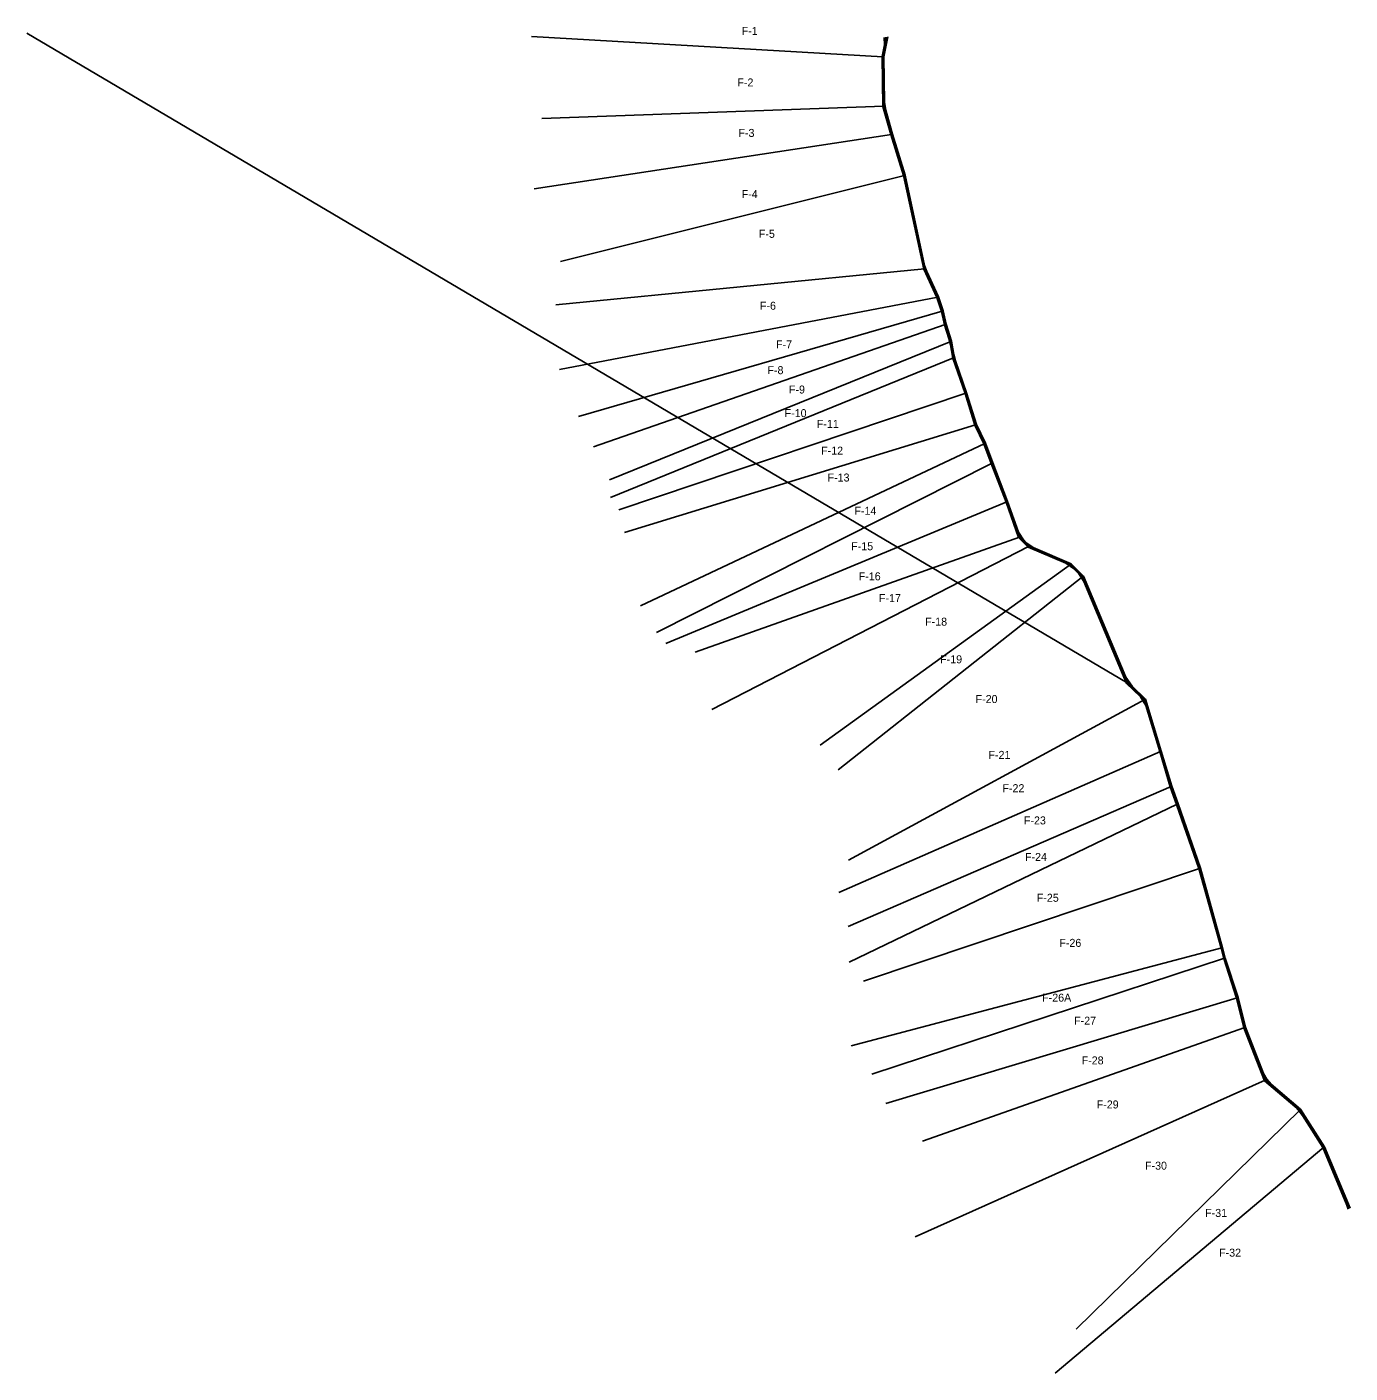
# Model space of a CAD drawing. Extents: x 449105 to 622091, y 1838803 to 1940013.
import ezdxf

# ---------------------------------------------------------------- set-up
doc = ezdxf.new("R2010")
doc.units = 0
for name, color, linetype in [('Level 50', 7, 'Continuous'), ('Level 6', 7, 'Continuous'), ('Level 63', 7, 'Continuous')]:
    doc.layers.add(name, color=color, linetype=linetype)

msp = doc.modelspace()

# ---------------------------------------------------------------- linework, layer by layer
at = {"layer": 'Level 50'}
for p, q in [((587345.381, 1939261.734), (587043.142, 1937770.604)), ((587090.522, 1939228.729), (587095.554, 1938658.427)), ((587214.345, 1939244.496), (587095.554, 1938658.427)), ((587095.554, 1938658.423), (586917.902, 1937781.958)), ((586917.902, 1937781.958), (586989.263, 1934037.384)), ((587043.142, 1937770.604), (587108.194, 1934357.092)), ((587108.194, 1934357.092), (587194.583, 1933764.378)), ((587108.194, 1934357.092), (587113.941, 1934055.538)), ((586989.263, 1934037.384), (587575.849, 1931919.542)), ((587113.941, 1934055.538), (587194.583, 1933764.378)), ((587194.582, 1933764.387), (587695.795, 1931954.78)), ((587575.849, 1931919.542), (588534.712, 1928831.802)), ((587695.795, 1931954.78), (588655.732, 1928863.58)), ((588534.712, 1928831.802), (590052.951, 1921801.885)), ((588655.732, 1928863.58), (590120.935, 1922079.236)), ((590120.933, 1922079.241), (590275.147, 1921622.052)), ((590120.933, 1922079.241), (590172.153, 1921842.077)), ((590052.951, 1921801.885), (591047.278, 1919677.72)), ((590172.153, 1921842.077), (590275.147, 1921622.052)), ((590275.146, 1921622.055), (591163.826, 1919723.582)), ((591047.278, 1919677.72), (591386.753, 1918624.845)), ((591163.826, 1919723.582), (591507.471, 1918657.777)), ((591386.753, 1918624.845), (591611.555, 1917624.298)), ((591507.471, 1918657.777), (591732.269, 1917657.244)), ((591611.555, 1917624.298), (591947.407, 1916582.25)), ((591732.269, 1917657.244), (592144.53, 1916378.124)), ((591947.41, 1916582.239), (592064.936, 1916106.092)), ((591947.41, 1916582.239), (592022.874, 1916348.098)), ((592022.874, 1916348.098), (592064.936, 1916106.092)), ((592064.935, 1916106.097), (592237.461, 1915113.457)), ((592144.53, 1916378.124), (592317.031, 1915385.624)), ((592237.461, 1915113.457), (593155.932, 1912462.15)), ((592317.028, 1915385.635), (592439.06, 1914913.385)), ((592317.028, 1915385.635), (592358.883, 1915144.825)), ((592358.883, 1915144.825), (592439.06, 1914913.385)), ((592439.062, 1914913.378), (593274.772, 1912500.972)), ((593155.932, 1912462.15), (593889.226, 1910068.692)), ((593274.772, 1912500.972), (594005.818, 1910114.85)), ((593889.226, 1910068.692), (594574.897, 1908672.859)), ((594005.818, 1910114.85), (594689.767, 1908722.523)), ((594574.897, 1908672.859), (595130.48, 1907194.846)), ((594689.767, 1908722.523), (595247.264, 1907239.416)), ((595130.48, 1907194.846), (596235.804, 1904291.723)), ((595247.264, 1907239.416), (596353.12, 1904334.899)), ((596235.804, 1904291.723), (597182.919, 1901622.115)), ((596353.12, 1904334.899), (597173.88, 1902021.444)), ((597173.881, 1902021.443), (597537.855, 1901439.936)), ((597173.881, 1902021.443), (597291.445, 1901690.067)), ((597182.919, 1901622.115), (597891.172, 1900903.164)), ((597291.445, 1901690.067), (597537.855, 1901439.936)), ((597401.352, 1901494.389), (597398.879, 1901491.952)), ((597537.857, 1901439.933), (597715.41, 1901259.699)), ((597715.407, 1901259.701), (598287.202, 1900869.559)), ((597715.407, 1901259.701), (597962.972, 1901008.398)), ((597891.172, 1900903.164), (600733.805, 1899685.91)), ((597962.972, 1901008.398), (598287.202, 1900869.559)), ((598287.207, 1900869.556), (601129.64, 1899652.387)), ((600733.8, 1899685.913), (601306.389, 1899296.494)), ((600733.8, 1899685.913), (601058.024, 1899547.075)), ((601058.024, 1899547.075), (601306.389, 1899296.494)), ((601129.64, 1899652.387), (602053.366, 1898720.417)), ((601306.384, 1899296.498), (601699.196, 1898900.182)), ((601699.197, 1898900.181), (602083.548, 1898324.212)), ((601699.197, 1898900.181), (601947.438, 1898649.725)), ((602053.366, 1898720.417), (605229.501, 1891124.537)), ((601947.438, 1898649.725), (602083.548, 1898324.212)), ((602083.547, 1898324.213), (605289.02, 1890658.17)), ((605229.501, 1891124.536), (605704.311, 1890437.737)), ((605229.501, 1891124.536), (605394.124, 1890730.832)), ((605289.02, 1890658.17), (606351.852, 1889653.903)), ((605394.124, 1890730.832), (605704.311, 1890437.737)), ((605704.311, 1890437.737), (606714.816, 1889482.913)), ((606351.852, 1889653.903), (606735.326, 1888985.801)), ((606351.852, 1889653.903), (606604.868, 1889414.829)), ((606604.868, 1889414.829), (606735.327, 1888985.798)), ((606714.816, 1889482.913), (607907.482, 1885560.671)), ((606735.326, 1888985.801), (607787.862, 1885524.391)), ((607907.482, 1885560.671), (608702.186, 1882920.43)), ((607787.862, 1885524.391), (608583.258, 1882881.852)), ((608583.258, 1882881.852), (609046.149, 1881554.503)), ((608702.186, 1882920.43), (609166.035, 1881590.337)), ((609046.149, 1881554.503), (610725.791, 1876732.743)), ((609166.035, 1881590.337), (610845.133, 1876770.139)), ((610725.791, 1876732.743), (612394.022, 1870750.855)), ((610845.133, 1876770.139), (612514.742, 1870783.307)), ((612394.022, 1870750.855), (612594.759, 1869975.148)), ((612514.742, 1870783.307), (612714.845, 1870010.054)), ((612594.759, 1869975.148), (613557.381, 1866997.202)), ((612714.845, 1870010.054), (613677.643, 1867031.56)), ((613557.381, 1866997.202), (614113.019, 1864765.931)), ((613677.643, 1867031.56), (614232.385, 1864803.891)), ((614113.019, 1864765.931), (615665.86, 1860783.541)), ((614232.385, 1864803.891), (615589.623, 1861323.14)), ((615589.622, 1861323.142), (615770.884, 1860858.281)), ((615589.622, 1861323.142), (615836.063, 1860904.666)), ((615665.86, 1860783.541), (617940.16, 1858845.981)), ((615770.884, 1860858.281), (616150.929, 1860534.505)), ((615836.063, 1860904.666), (616150.928, 1860534.507)), ((616150.927, 1860534.509), (618378.838, 1858636.468)), ((617940.159, 1858845.982), (618283.386, 1858553.574)), ((617940.159, 1858845.982), (618245.635, 1858520.79)), ((618245.635, 1858520.79), (618524.581, 1858173.036)), ((618283.386, 1858553.574), (618524.581, 1858173.036)), ((618378.838, 1858636.468), (620164.3, 1855819.519)), ((618524.587, 1858173.029), (620053.004, 1855761.623)), ((620053.004, 1855761.623), (621854.506, 1851433.946)), ((620164.3, 1855819.519), (622091.479, 1851189.935)), ((621854.505, 1851433.949), (621942.697, 1851135.293)), ((621854.505, 1851433.949), (621970.905, 1851154.327))]:
    msp.add_line(p, q, dxfattribs=at)
at = {"layer": 'Level 6'}
for p, q in [((587279.863, 1939253.115), (586980.522, 1937776.281)), ((586980.522, 1937776.281), (587051.602, 1934046.461)), ((587051.602, 1934046.461), (587635.822, 1931937.161)), ((587635.822, 1931937.161), (588595.222, 1928847.691)), ((588595.222, 1928847.691), (590112.552, 1921821.981)), ((590112.552, 1921821.981), (591105.552, 1919700.651)), ((591105.552, 1919700.651), (591447.112, 1918641.311)), ((591447.112, 1918641.311), (591671.912, 1917640.771)), ((591671.912, 1917640.771), (592083.702, 1916363.111)), ((592083.702, 1916363.111), (592298.172, 1915129.141)), ((592298.172, 1915129.141), (593215.352, 1912481.561)), ((593215.352, 1912481.561), (593947.522, 1910091.771)), ((593947.522, 1910091.771), (594632.332, 1908697.691)), ((594632.332, 1908697.691), (595188.872, 1907217.131)), ((595188.872, 1907217.131), (596294.462, 1904313.311)), ((596294.462, 1904313.311), (597237.182, 1901656.091)), ((597237.182, 1901656.091), (597927.072, 1900955.781)), ((597927.072, 1900955.781), (601093.832, 1899599.731)), ((601093.832, 1899599.731), (602000.402, 1898685.071)), ((602000.402, 1898685.071), (605341.572, 1890694.501)), ((605341.572, 1890694.501), (606659.842, 1889448.871)), ((606659.842, 1889448.871), (607847.672, 1885542.531)), ((607847.672, 1885542.531), (608642.722, 1882901.141)), ((608642.722, 1882901.141), (609106.092, 1881572.421)), ((609106.092, 1881572.421), (610785.462, 1876751.441)), ((610785.462, 1876751.441), (612454.382, 1870767.081)), ((612454.382, 1870767.081), (612654.802, 1869992.601)), ((612654.802, 1869992.601), (613617.512, 1867014.381)), ((613617.512, 1867014.381), (614172.702, 1864784.911)), ((614172.702, 1864784.911), (615718.372, 1860820.911)), ((615718.372, 1860820.911), (618331.112, 1858595.021)), ((618331.112, 1858595.021), (620108.652, 1855790.571)), ((620108.652, 1855790.571), (622031.192, 1851172.131))]:
    msp.add_line(p, q, dxfattribs=at)
at = {"layer": 'Level 63'}
for p, q in [((605341.572, 1890694.501), (522658.154, 1939543.582)), ((586980.522, 1937776.281), (560566.281, 1939287.327)), ((587051.602, 1934046.461), (561344.073, 1933133.699)), ((587635.822, 1931937.161), (560778.406, 1927828.846)), ((588595.222, 1928847.691), (562758.239, 1922382.532)), ((590112.552, 1921821.981), (562404.697, 1919128.889)), ((591105.552, 1919700.651), (562687.531, 1914248.425)), ((591447.112, 1918641.311), (564101.697, 1910711.857)), ((591671.912, 1917640.771), (565233.03, 1908448.453)), ((592083.702, 1916363.111), (566435.071, 1905972.856)), ((592298.172, 1915129.141), (566505.78, 1904628.96)), ((593215.352, 1912481.561), (567142.155, 1903709.452)), ((593947.522, 1910091.771), (567566.404, 1902011.899)), ((594632.332, 1908697.691), (568762.383, 1896476.232)), ((595188.872, 1907217.131), (569964.424, 1894494.776)), ((596294.462, 1904313.311), (570671.507, 1893645.581)), ((597237.182, 1901656.091), (572863.465, 1893008.684)), ((597927.072, 1900955.781), (574136.215, 1888691.94)), ((601093.832, 1899599.731), (582267.671, 1886002.821)), ((602000.402, 1898685.071), (583611.129, 1884162.897)), ((606659.842, 1889448.871), (584388.92, 1877369.332)), ((607847.672, 1885542.531), (583677.745, 1874929.279)), ((608642.722, 1882901.141), (584384.828, 1872381.693)), ((609106.092, 1881572.421), (584455.537, 1869692.573)), ((610785.462, 1876751.441), (585516.161, 1868277.248)), ((612454.382, 1870767.081), (584596.953, 1863394.373)), ((612654.802, 1869992.601), (586152.536, 1861271.384)), ((613617.512, 1867014.381), (587213.161, 1859077.629)), ((614172.702, 1864784.911), (589970.785, 1856246.977)), ((615718.372, 1860820.911), (589407.847, 1849041.661)), ((618331.112, 1858595.021), (601498.969, 1842106.564)), ((620108.652, 1855790.571), (599934.746, 1838802.698))]:
    msp.add_line(p, q, dxfattribs=at)

# ---------------------------------------------------------------- texts
for s, p in [('F-1', (576370.689, 1939413.326)), ('F-2', (576047.92, 1935538.84)), ('F-3', (576128.612, 1931745.073)), ('F-4', (576370.689, 1927144.121)), ('F-5', (577661.763, 1924157.538)), ('F-6', (577742.455, 1918749.402)), ('F-7', (578952.837, 1915843.538)), ('F-8', (578307.3, 1913906.295)), ('F-9', (579921.143, 1912453.363)), ('F-10', (579598.375, 1910677.557)), ('F-11', (582019.139, 1909870.372)), ('F-12', (582341.908, 1907852.411)), ('F-13', (582826.061, 1905834.45)), ('F-14', (584843.364, 1903332.178)), ('F-15', (584601.288, 1900668.469)), ('F-16', (585166.133, 1898408.352)), ('F-17', (586687.349, 1896771.152)), ('F-18', (590157.112, 1894994.469)), ('F-19', (591286.802, 1892167.927)), ('F-20', (593949.643, 1889179.87)), ('F-21', (594917.948, 1884980.437)), ('F-22', (595966.946, 1882476.929)), ('F-23', (597580.789, 1880054.179)), ('F-24', (597661.482, 1877308.397)), ('F-25', (598549.095, 1874239.58)), ('F-26', (600243.63, 1870847.731)), ('F-26A', (598952.556, 1866729.057)), ('F-27', (601355.591, 1864999.009)), ('F-28', (601920.436, 1862010.951)), ('F-29', (603050.126, 1858699.86)), ('F-30', (606681.273, 1854096.636)), ('F-31', (611200.033, 1850543.269)), ('F-32', (612249.031, 1847555.212))]:
    msp.add_text(s, height=600, dxfattribs=at).set_placement(p)

doc.saveas('drawing.dxf')
